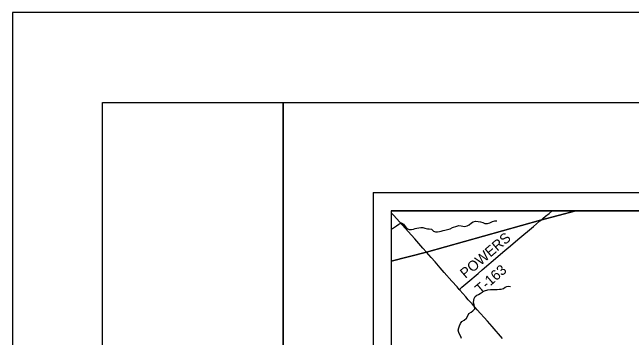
# Model space of a CAD drawing. Extents: x 0 to 34, y 0 to 22.
# Drawn here: x 0 to 3.432, y 20.196 to 22 of the extents above; entities that cross this region are included whole.
import ezdxf

# ---------------------------------------------------------------- set-up
doc = ezdxf.new("R2010")
doc.units = 0
for name, color, linetype in [('Default', 7, 'Continuous'), ('GM_X_Minor_River', 7, 'Continuous'), ('GM_X_Township_Road', 7, 'Continuous'), ('GM_X_Township_Road_Text', 7, 'Continuous'), ('SH_Border', 7, 'Continuous'), ('SH_Cut_Line', 7, 'Continuous'), ('SH_Data', 7, 'Continuous')]:
    doc.layers.add(name, color=color, linetype=linetype)

msp = doc.modelspace()

# ---------------------------------------------------------------- linework, layer by layer
at = {"layer": 'Default'}
msp.add_lwpolyline([(6.6858, 19.0362), (6.6949, 19.1537), (6.8302, 20.9), (3.1229, 20.9), (2.9275, 20.8467), (2.2946, 20.6707), (2.1, 20.6202), (2.1, 17.1279), (2.1211, 17.1003), (3.2076, 15.5689), (3.4902, 15.1704), (4.0558, 14.3671), (4.1658, 14.2105), (4.302, 14.3105), (5.6165, 15.2674), (6.0871, 15.6176), (6.2834, 15.7529), (6.4392, 15.8657), (6.5428, 17.1931), (6.5451, 17.2211), (6.6309, 18.3364), (6.6363, 18.3979), (6.6654, 18.7733)], dxfattribs=at)
msp.add_lwpolyline([(3.1229, 20.9), (2.1, 20.9), (2.1, 20.6202), (2.2946, 20.6707), (2.9275, 20.8467)], close=True, dxfattribs=at)
at = {"layer": 'GM_X_Minor_River'}
for points in [[(2.1, 20.7982), (2.1062, 20.8018), (2.1173, 20.8085), (2.1292, 20.8156), (2.1422, 20.8257), (2.1564, 20.8331), (2.1681, 20.8254), (2.1763, 20.8131), (2.1861, 20.802), (2.1989, 20.7954), (2.2111, 20.7949), (2.2222, 20.797), (2.2317, 20.8004), (2.2413, 20.8037), (2.2523, 20.8058), (2.263, 20.8065), (2.2744, 20.806), (2.2858, 20.8039), (2.3002, 20.7996), (2.3101, 20.8002), (2.323, 20.7982), (2.3335, 20.7863), (2.3456, 20.7827), (2.3552, 20.7834), (2.3662, 20.784), (2.3765, 20.7862), (2.3868, 20.7899), (2.3967, 20.7928), (2.4105, 20.7949), (2.4265, 20.7993), (2.4399, 20.806), (2.4628, 20.8149), (2.4735, 20.8178), (2.4864, 20.8169), (2.4963, 20.8145), (2.5073, 20.8132), (2.5211, 20.8169), (2.531, 20.8217), (2.5441, 20.8326), (2.5537, 20.8381), (2.5666, 20.8422), (2.5811, 20.8409), (2.5944, 20.8373), (2.6073, 20.8341), (2.619, 20.8291), (2.6331, 20.8285), (2.6464, 20.8329), (2.661, 20.8404), (2.6732, 20.844), (2.6854, 20.8443)], [(2.4892, 20.1911), (2.4844, 20.2021), (2.4773, 20.2151), (2.4744, 20.225), (2.4707, 20.238), (2.4736, 20.2505), (2.4779, 20.2607), (2.4841, 20.274), (2.49, 20.286), (2.5041, 20.2935), (2.516, 20.304), (2.5234, 20.3172), (2.5289, 20.3304), (2.5427, 20.3375), (2.5523, 20.3439), (2.5623, 20.3548), (2.5617, 20.3677), (2.5588, 20.3776), (2.5555, 20.3909), (2.5568, 20.4035), (2.5588, 20.4137), (2.5639, 20.4235), (2.5735, 20.4306), (2.5831, 20.4351), (2.5926, 20.4411), (2.6034, 20.4474), (2.6164, 20.4556), (2.6355, 20.4611), (2.65, 20.4632), (2.6606, 20.4635), (2.6701, 20.4634), (2.6873, 20.4628), (2.6991, 20.4638), (2.7094, 20.4656), (2.7208, 20.4692), (2.7312, 20.476), (2.7407, 20.48), (2.751, 20.4811), (2.7609, 20.4791)]]:
    msp.add_lwpolyline(points, dxfattribs=at)
at = {"layer": 'GM_X_Township_Road'}
for points in [[(2.9278, 20.8462), (2.9401, 20.8567), (2.9542, 20.8689), (2.9739, 20.8851), (2.9914, 20.9)], [(2.2948, 20.6702), (2.2751, 20.6928), (2.2297, 20.7439), (2.1938, 20.7844), (2.1627, 20.8191), (2.1146, 20.8728), (2.1, 20.8888)], [(2.4765, 20.4629), (2.4826, 20.4683), (2.49, 20.4749), (2.5232, 20.503), (2.5805, 20.5518), (2.6036, 20.5715), (2.69, 20.6454), (2.7178, 20.6692), (2.7407, 20.6884), (2.76, 20.7051), (2.8015, 20.7396), (2.8884, 20.813), (2.9216, 20.841), (2.9278, 20.8462)], [(2.4765, 20.4629), (2.4644, 20.4771), (2.4362, 20.5094), (2.3935, 20.5579), (2.371, 20.5836), (2.3427, 20.6158), (2.3214, 20.6401), (2.2948, 20.6702)], [(2.7158, 20.191), (2.6585, 20.2573), (2.6322, 20.287), (2.5758, 20.3508), (2.5474, 20.3829), (2.5266, 20.406), (2.5127, 20.4219), (2.4802, 20.4587), (2.4765, 20.4629)]]:
    msp.add_lwpolyline(points, dxfattribs=at)
at = {"layer": 'SH_Border'}
for points in [[(0.5, 21.5), (1.5, 21.5), (1.5, 0.5), (0.5, 0.5)], [(1.5, 21.5), (33.5, 21.5), (33.5, 0.5), (1.5, 0.5)]]:
    msp.add_lwpolyline(points, close=True, dxfattribs=at)
at = {"layer": 'SH_Cut_Line'}
msp.add_lwpolyline([(0, 0), (34, 0), (34, 22), (0, 22)], close=True, dxfattribs=at)
msp.add_lwpolyline([(6.6858, 19.0362), (6.6949, 19.1537), (6.8302, 20.9), (2.1, 20.9), (2.1, 14.1), (4.022, 14.1), (4.1658, 14.2105), (4.302, 14.3105), (5.6165, 15.2674), (6.0871, 15.6176), (6.2834, 15.7529), (6.4392, 15.8657), (6.5428, 17.1931), (6.5451, 17.2211), (6.6309, 18.3364), (6.6363, 18.3979), (6.6654, 18.7733)], dxfattribs=at)
at = {"layer": 'SH_Data'}
for p, q in [((2, 21), (9, 21)), ((2, 21), (2, 14)), ((2.1, 20.9), (2.1, 14.1)), ((2.1, 20.9), (8.9, 20.9))]:
    msp.add_line(p, q, dxfattribs=at)

# ---------------------------------------------------------------- texts
at = {"layer": 'GM_X_Township_Road_Text'}
for s, rotation, p in [('POWERS', 40.564, (2.5109, 20.5213)), ('T-163', 40.6316, (2.5938, 20.4336))]:
    msp.add_text(s, height=0.05682, rotation=rotation, dxfattribs=at).set_placement(p)

doc.saveas('drawing.dxf')
